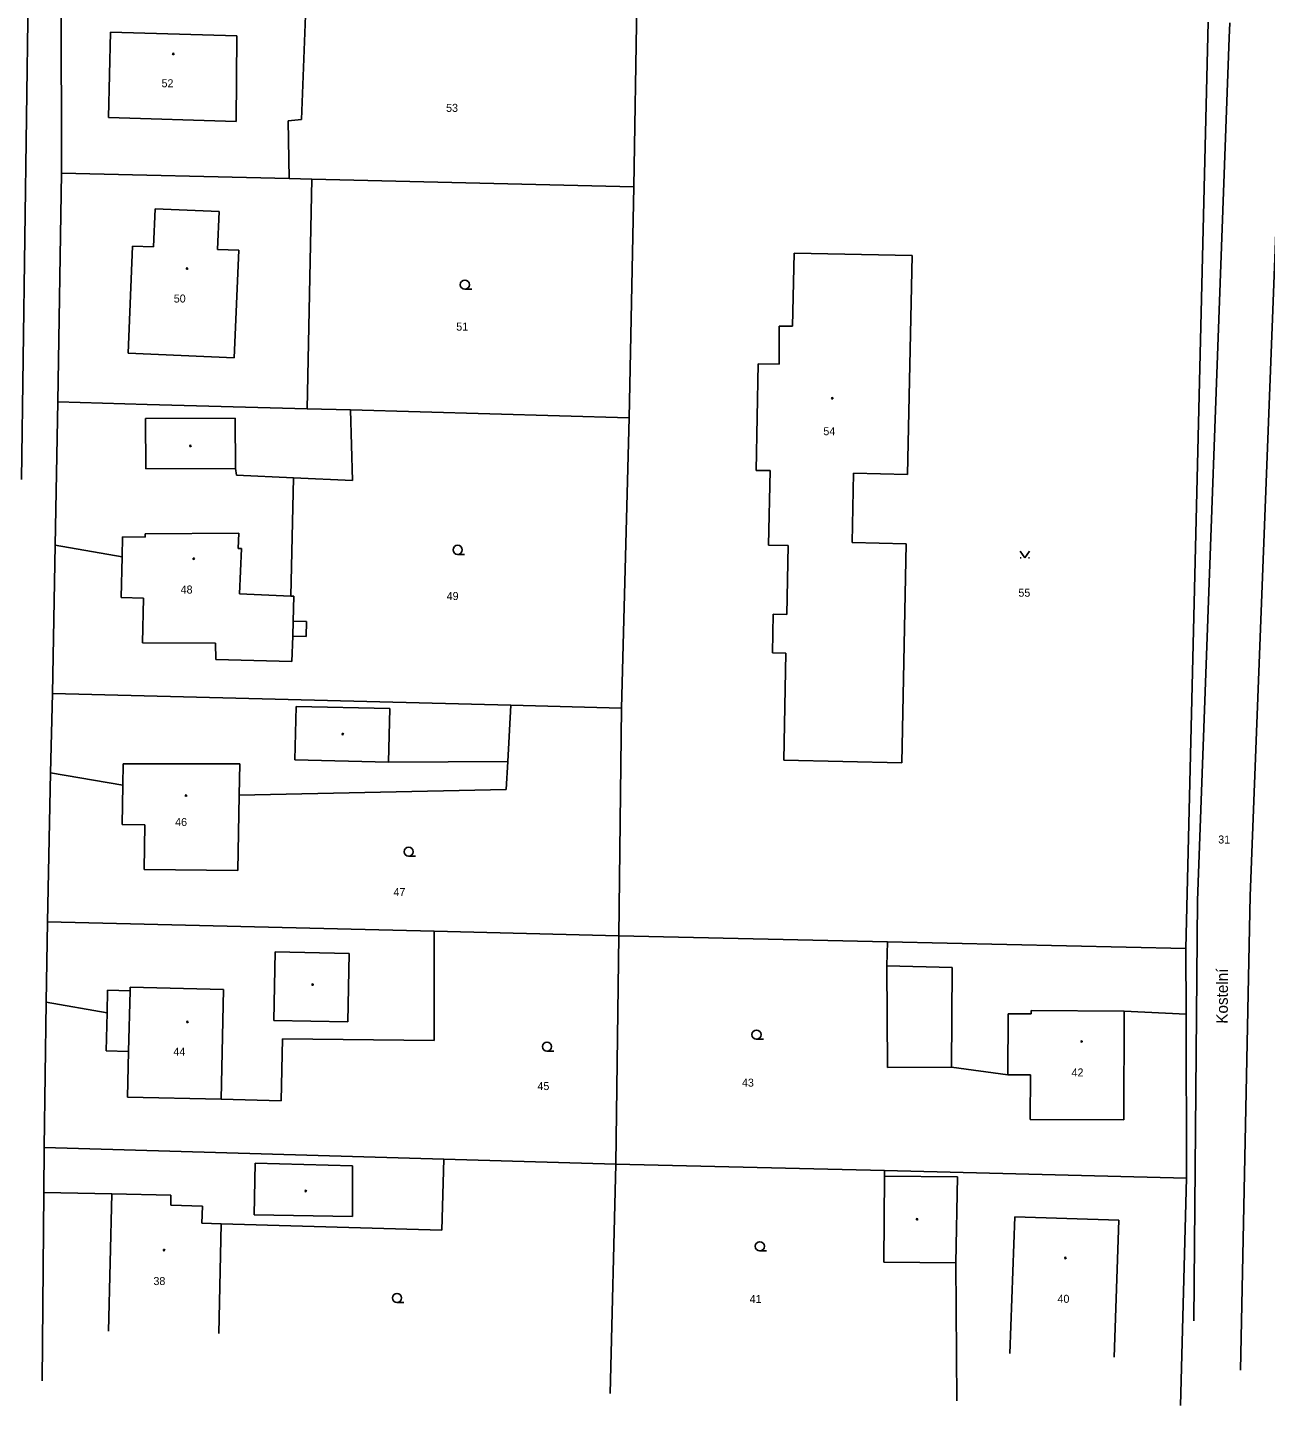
# Model space of a CAD drawing. Extents: x -454285 to -453563, y -1108687 to -1108249.
# Drawn here: x -453869.2 to -453760.9, y -1108667.8 to -1108547.2 of the extents above; entities that cross this region are included whole.
import ezdxf

# ---------------------------------------------------------------- set-up
doc = ezdxf.new("R2010")
doc.units = 0
for name, color, linetype in [('1', 7, 'Continuous'), ('14', 7, 'Continuous'), ('15', 7, 'Continuous'), ('2', 7, 'Continuous'), ('23', 7, 'Continuous'), ('25', 7, 'Continuous'), ('38', 7, 'Continuous')]:
    doc.layers.add(name, color=color, linetype=linetype)

# ---------------------------------------------------------------- blocks, each defined once
blk = doc.blocks.new('Z402')
for start, end in [(0, 180), (180, 0)]:
    blk.add_arc((0, 0), 0.15, start, end)
blk = doc.blocks.new('Z3040')
blk.add_line((1.5, 0), (0, 0))
blk.add_circle((0, 1), 1)
blk = doc.blocks.new('Z3140')
for p, q in [((-1, 1.5), (0, 0)), ((-1, 0), (-0.8, 0)), ((0, 0), (1, 1.5)), ((0.8, 0), (1, 0))]:
    blk.add_line(p, q)

msp = doc.modelspace()

# ---------------------------------------------------------------- linework, layer by layer
at = {"layer": '1'}
for p, q in [((-453866.25, -1108559.95), (-453866.27, -1108544.19)), ((-453844.85, -1108544.61), (-453845.24, -1108555.25)), ((-453816.18, -1108561.15), (-453815.92, -1108545.18)), ((-453765.93, -1108546.74), (-453767.89, -1108627.79)), ((-453845.24, -1108555.25), (-453846.4, -1108555.38)), ((-453846.4, -1108555.38), (-453846.32, -1108560.43)), ((-453866.25, -1108559.95), (-453866.55, -1108579.96)), ((-453866.25, -1108559.95), (-453846.32, -1108560.43)), ((-453846.32, -1108560.43), (-453844.33, -1108560.48)), ((-453844.33, -1108560.48), (-453844.76, -1108580.57)), ((-453844.33, -1108560.48), (-453816.18, -1108561.15)), ((-453816.18, -1108561.15), (-453816.6, -1108581.35)), ((-453802.16, -1108566.95), (-453802.29, -1108573.35)), ((-453791.83, -1108567.17), (-453802.16, -1108566.95)), ((-453792.23, -1108586.31), (-453791.83, -1108567.17)), ((-453803.47, -1108573.33), (-453803.48, -1108576.67)), ((-453802.29, -1108573.35), (-453803.47, -1108573.33)), ((-453805.3, -1108576.63), (-453805.49, -1108585.96)), ((-453803.48, -1108576.67), (-453805.3, -1108576.63)), ((-453866.55, -1108579.96), (-453866.79, -1108592.5)), ((-453858.75, -1108580.18), (-453866.55, -1108579.96)), ((-453844.76, -1108580.57), (-453858.75, -1108580.18)), ((-453840.96, -1108580.67), (-453844.76, -1108580.57)), ((-453840.79, -1108586.85), (-453840.96, -1108580.67)), ((-453816.6, -1108581.35), (-453840.96, -1108580.67)), ((-453817.25, -1108606.76), (-453816.6, -1108581.35)), ((-453805.49, -1108585.96), (-453804.26, -1108585.98)), ((-453804.39, -1108592.49), (-453804.26, -1108585.98)), ((-453846.18, -1108596.96), (-453845.96, -1108586.61)), ((-453845.96, -1108586.61), (-453840.79, -1108586.85)), ((-453797.09, -1108592.28), (-453796.96, -1108586.21)), ((-453796.96, -1108586.21), (-453792.23, -1108586.31)), ((-453866.79, -1108592.5), (-453867.04, -1108605.48)), ((-453866.79, -1108592.5), (-453860.94, -1108593.52)), ((-453802.67, -1108592.53), (-453804.39, -1108592.49)), ((-453802.8, -1108598.57), (-453802.67, -1108592.53)), ((-453792.35, -1108592.38), (-453797.09, -1108592.28)), ((-453792.75, -1108611.54), (-453792.35, -1108592.38)), ((-453860.94, -1108593.52), (-453861.01, -1108597.08)), ((-453861.01, -1108597.08), (-453859.07, -1108597.13)), ((-453859.07, -1108597.13), (-453859.17, -1108601.03)), ((-453845.93, -1108596.97), (-453846.18, -1108596.96)), ((-453845.99, -1108599.16), (-453845.93, -1108596.97)), ((-453844.81, -1108599.19), (-453845.99, -1108599.16)), ((-453844.85, -1108600.48), (-453844.81, -1108599.19)), ((-453804.06, -1108601.92), (-453803.99, -1108598.54)), ((-453803.99, -1108598.54), (-453802.8, -1108598.57)), ((-453846.08, -1108602.68), (-453846.02, -1108600.46)), ((-453846.02, -1108600.46), (-453844.85, -1108600.48)), ((-453859.17, -1108601.03), (-453852.76, -1108601.06)), ((-453852.76, -1108601.06), (-453852.74, -1108602.5)), ((-453852.74, -1108602.5), (-453846.08, -1108602.68)), ((-453802.87, -1108601.95), (-453804.06, -1108601.92)), ((-453803.07, -1108611.32), (-453802.87, -1108601.95)), ((-453867.04, -1108605.48), (-453867.19, -1108612.42)), ((-453826.94, -1108606.51), (-453867.04, -1108605.48)), ((-453827.21, -1108611.43), (-453826.94, -1108606.51)), ((-453817.25, -1108606.76), (-453826.94, -1108606.51)), ((-453817.48, -1108626.67), (-453817.25, -1108606.76)), ((-453803.07, -1108611.32), (-453792.75, -1108611.54)), ((-453867.19, -1108612.42), (-453867.46, -1108625.44)), ((-453867.19, -1108612.42), (-453860.89, -1108613.49)), ((-453827.35, -1108613.88), (-453827.21, -1108611.43)), ((-453860.89, -1108613.49), (-453860.93, -1108616.95)), ((-453850.81, -1108620.97), (-453850.7, -1108614.38)), ((-453850.7, -1108614.38), (-453827.35, -1108613.88)), ((-453858.96, -1108616.98), (-453860.93, -1108616.95)), ((-453859, -1108620.88), (-453858.96, -1108616.98)), ((-453850.81, -1108620.97), (-453859, -1108620.88)), ((-453867.46, -1108625.44), (-453867.57, -1108632.48)), ((-453833.63, -1108626.27), (-453867.46, -1108625.44)), ((-453833.63, -1108635.82), (-453833.63, -1108626.27)), ((-453833.63, -1108626.27), (-453817.48, -1108626.67)), ((-453817.48, -1108626.67), (-453817.74, -1108646.64)), ((-453793.99, -1108627.2), (-453817.48, -1108626.67)), ((-453794.04, -1108629.3), (-453793.99, -1108627.2)), ((-453767.89, -1108627.79), (-453793.99, -1108627.2)), ((-453767.87, -1108633.53), (-453767.89, -1108627.79)), ((-453794.04, -1108629.3), (-453794, -1108638.2)), ((-453867.76, -1108645.2), (-453867.57, -1108632.48)), ((-453867.57, -1108632.48), (-453862.26, -1108633.41)), ((-453862.26, -1108633.41), (-453862.33, -1108636.75)), ((-453773.28, -1108633.28), (-453773.32, -1108642.78)), ((-453767.87, -1108633.53), (-453773.28, -1108633.28)), ((-453767.83, -1108647.87), (-453767.87, -1108633.53)), ((-453847.03, -1108641.1), (-453846.92, -1108635.7)), ((-453846.92, -1108635.7), (-453833.63, -1108635.82)), ((-453860.39, -1108636.8), (-453862.33, -1108636.75)), ((-453860.48, -1108640.78), (-453860.39, -1108636.8)), ((-453794, -1108638.2), (-453788.38, -1108638.17)), ((-453788.38, -1108638.17), (-453783.45, -1108638.83)), ((-453781.48, -1108638.84), (-453783.45, -1108638.83)), ((-453781.5, -1108642.75), (-453781.48, -1108638.84)), ((-453860.48, -1108640.78), (-453852.28, -1108640.98)), ((-453852.28, -1108640.98), (-453847.03, -1108641.1)), ((-453773.32, -1108642.78), (-453781.5, -1108642.75)), ((-453867.76, -1108645.2), (-453867.79, -1108649.12)), ((-453832.8, -1108646.21), (-453867.76, -1108645.2)), ((-453832.8, -1108646.21), (-453832.98, -1108652.43)), ((-453817.74, -1108646.64), (-453832.8, -1108646.21)), ((-453817.74, -1108646.64), (-453818.24, -1108666.71)), ((-453817.74, -1108646.64), (-453794.24, -1108647.22)), ((-453794.24, -1108647.22), (-453767.83, -1108647.87)), ((-453794.24, -1108647.22), (-453794.24, -1108647.71)), ((-453794.31, -1108655.23), (-453794.24, -1108647.71)), ((-453767.83, -1108647.87), (-453768.37, -1108667.76)), ((-453867.79, -1108649.12), (-453867.94, -1108665.61)), ((-453867.79, -1108649.12), (-453861.85, -1108649.26)), ((-453861.85, -1108649.26), (-453862.12, -1108661.26)), ((-453852.49, -1108661.47), (-453852.27, -1108651.86)), ((-453832.98, -1108652.43), (-453852.27, -1108651.86)), ((-453788.02, -1108655.29), (-453794.31, -1108655.23)), ((-453787.92, -1108667.35), (-453788.02, -1108655.29))]:
    msp.add_line(p, q, dxfattribs=at)
at = {"layer": '2'}
for p, q in [((-453869.73, -1108586.75), (-453869.15, -1108543.86)), ((-453764.11, -1108548.12), (-453764.05, -1108546.8)), ((-453862.13, -1108555.08), (-453861.96, -1108547.63)), ((-453861.96, -1108547.63), (-453850.9, -1108547.94)), ((-453850.9, -1108547.94), (-453850.96, -1108555.42)), ((-453766.88, -1108623.58), (-453764.11, -1108548.12)), ((-453759.39, -1108548.56), (-453762.28, -1108623.18)), ((-453850.96, -1108555.42), (-453862.13, -1108555.08)), ((-453858.19, -1108566.41), (-453858.05, -1108563.08)), ((-453858.05, -1108563.08), (-453852.45, -1108563.32)), ((-453852.45, -1108563.32), (-453852.59, -1108566.62)), ((-453860.42, -1108575.7), (-453860.02, -1108566.33)), ((-453860.02, -1108566.33), (-453858.19, -1108566.41)), ((-453852.59, -1108566.62), (-453850.73, -1108566.69)), ((-453851.13, -1108576.1), (-453850.73, -1108566.69)), ((-453860.42, -1108575.7), (-453851.13, -1108576.1)), ((-453858.89, -1108581.43), (-453851.05, -1108581.4)), ((-453858.87, -1108585.83), (-453858.89, -1108581.43)), ((-453851.05, -1108581.4), (-453851.03, -1108585.8)), ((-453851.03, -1108585.8), (-453858.87, -1108585.83)), ((-453851.03, -1108585.8), (-453850.94, -1108586.38)), ((-453845.96, -1108586.61), (-453850.94, -1108586.38)), ((-453860.91, -1108591.78), (-453860.94, -1108593.52)), ((-453858.93, -1108591.81), (-453860.91, -1108591.78)), ((-453858.92, -1108591.52), (-453858.93, -1108591.81)), ((-453850.74, -1108591.46), (-453858.92, -1108591.52)), ((-453850.79, -1108592.79), (-453850.74, -1108591.46)), ((-453850.51, -1108592.8), (-453850.79, -1108592.79)), ((-453850.67, -1108596.77), (-453850.51, -1108592.8)), ((-453846.18, -1108596.96), (-453850.67, -1108596.77)), ((-453845.99, -1108599.16), (-453846.02, -1108600.46)), ((-453845.84, -1108611.27), (-453845.72, -1108606.6)), ((-453845.72, -1108606.6), (-453837.51, -1108606.8)), ((-453837.51, -1108606.8), (-453837.63, -1108611.48)), ((-453837.63, -1108611.48), (-453845.84, -1108611.27)), ((-453860.89, -1108613.49), (-453860.86, -1108611.63)), ((-453860.86, -1108611.63), (-453850.65, -1108611.62)), ((-453850.7, -1108614.38), (-453850.65, -1108611.62)), ((-453837.63, -1108611.48), (-453827.21, -1108611.43)), ((-453762.28, -1108623.18), (-453763.11, -1108664.67)), ((-453767.2, -1108660.35), (-453766.88, -1108623.58)), ((-453847.66, -1108634.07), (-453847.54, -1108628.08)), ((-453847.54, -1108628.08), (-453841.07, -1108628.22)), ((-453841.07, -1108628.22), (-453841.2, -1108634.2)), ((-453788.32, -1108629.45), (-453794.04, -1108629.3)), ((-453788.38, -1108638.17), (-453788.32, -1108629.45)), ((-453862.26, -1108633.41), (-453862.21, -1108631.44)), ((-453862.21, -1108631.44), (-453860.24, -1108631.48)), ((-453860.39, -1108636.8), (-453860.24, -1108631.48)), ((-453860.24, -1108631.48), (-453860.23, -1108631.18)), ((-453860.23, -1108631.18), (-453852.08, -1108631.38)), ((-453852.08, -1108631.38), (-453852.28, -1108640.98)), ((-453841.2, -1108634.2), (-453847.66, -1108634.07)), ((-453783.43, -1108633.5), (-453783.45, -1108638.83)), ((-453783.43, -1108633.5), (-453781.43, -1108633.51)), ((-453781.43, -1108633.51), (-453781.43, -1108633.21)), ((-453781.43, -1108633.21), (-453773.28, -1108633.28)), ((-453849.38, -1108651.08), (-453849.3, -1108646.56)), ((-453849.3, -1108646.56), (-453840.78, -1108646.8)), ((-453840.78, -1108646.8), (-453840.78, -1108651.24)), ((-453794.24, -1108647.71), (-453787.86, -1108647.75)), ((-453787.86, -1108647.75), (-453788.02, -1108655.29)), ((-453861.85, -1108649.26), (-453856.67, -1108649.37)), ((-453856.67, -1108649.37), (-453856.69, -1108650.23)), ((-453856.69, -1108650.23), (-453853.92, -1108650.32)), ((-453853.92, -1108650.32), (-453853.96, -1108651.82)), ((-453840.78, -1108651.24), (-453849.38, -1108651.08)), ((-453853.96, -1108651.82), (-453852.27, -1108651.86)), ((-453783.28, -1108663.22), (-453782.85, -1108651.25)), ((-453782.85, -1108651.25), (-453773.76, -1108651.56)), ((-453773.76, -1108651.56), (-453774.17, -1108663.53))]:
    msp.add_line(p, q, dxfattribs=at)

# ---------------------------------------------------------------- block references
at = {"layer": '23', "xscale": 0.4, "yscale": 0.4000000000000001}
for name, p in [('Z3040', (-453830.96, -1108570.11)), ('Z3040', (-453831.59, -1108593.31)), ('Z3140', (-453781.98, -1108593.62)), ('Z3040', (-453835.88, -1108619.72)), ('Z3040', (-453805.45, -1108635.72)), ('Z3040', (-453823.78, -1108636.77)), ('Z3040', (-453805.16, -1108654.24)), ('Z3040', (-453836.89, -1108658.76))]:
    msp.add_blockref(name, p, dxfattribs=at)
at = {"layer": '25', "xscale": 0.4, "yscale": 0.4000000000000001}
for p in [(-453856.46, -1108549.52), (-453855.25, -1108568.3), (-453798.82, -1108579.65), (-453854.96, -1108583.81), (-453854.67, -1108593.69), (-453841.64, -1108609.03), (-453855.35, -1108614.41), (-453844.28, -1108630.94), (-453855.23, -1108634.21), (-453777.01, -1108635.92), (-453844.88, -1108649), (-453791.4, -1108651.47), (-453857.27, -1108654.17), (-453778.43, -1108654.86)]:
    msp.add_blockref('Z402', p, dxfattribs=at)

# ---------------------------------------------------------------- texts
at = {"layer": '14'}
for s, p in [('53', (-453832.6, -1108554.59)), ('51', (-453831.71, -1108573.73)), ('49', (-453832.55, -1108597.3)), ('55', (-453782.54, -1108597.01)), ('31', (-453765.06, -1108618.6)), ('47', (-453837.2, -1108623.19)), ('45', (-453824.61, -1108640.17)), ('43', (-453806.72, -1108639.87)), ('41', (-453806.05, -1108658.8))]:
    msp.add_text(s, height=0.7, dxfattribs=at).set_placement(p)
at = {"layer": '15'}
for s, p in [('52', (-453857.49, -1108552.44)), ('50', (-453856.42, -1108571.27)), ('54', (-453799.6, -1108582.88)), ('48', (-453855.82, -1108596.73)), ('46', (-453856.3, -1108617.07)), ('44', (-453856.45, -1108637.15)), ('42', (-453777.89, -1108638.98)), ('38', (-453858.2, -1108657.23)), ('40', (-453779.12, -1108658.78))]:
    msp.add_text(s, height=0.7, dxfattribs=at).set_placement(p)
at = {"layer": '38'}
msp.add_text('Kostelní', height=1, rotation=89.721, dxfattribs=at).set_placement((-453764.23, -1108634.37))

doc.saveas('drawing.dxf')
